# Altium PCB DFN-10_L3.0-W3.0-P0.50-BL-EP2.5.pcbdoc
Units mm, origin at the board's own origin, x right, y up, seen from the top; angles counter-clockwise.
Board outline 15.85 x 16.55 mm, 2 copper layers (Top Layer, Bottom Layer), stack 0 mm thick; 1 components, 0 nets, 11 pads, 0 vias.
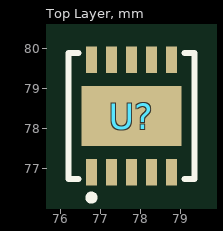
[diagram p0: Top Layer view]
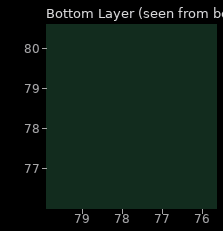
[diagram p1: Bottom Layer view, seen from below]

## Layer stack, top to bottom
Top Layer: signal copper (thickness not stored)
Bottom Layer: signal copper (thickness not stored)

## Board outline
85.702,69.85 69.85,69.85 69.85,86.405 85.702,86.405

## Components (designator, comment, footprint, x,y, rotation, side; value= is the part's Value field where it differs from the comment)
U? "" DFN-10_L3.0-W3.0-P0.50-BL-EP2.5 77.776,78.315 r0 top

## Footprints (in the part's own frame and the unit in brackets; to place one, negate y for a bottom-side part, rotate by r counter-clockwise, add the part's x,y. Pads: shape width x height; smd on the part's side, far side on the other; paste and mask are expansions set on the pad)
DFN-10_L3.0-W3.0-P0.50-BL-EP2.5 [mm]
  rect 0.28x0.665 smd paste+0 mask+0.05: 1(-1,-1.407) 2(-0.5,-1.407) 3(0,-1.407) 4(0.5,-1.407) 5(1,-1.407) 6(1,1.407) 7(0.5,1.407) 8(0,1.407) 9(-0.5,1.407) 10(-1,1.407)
  rect 2.5x1.5 smd paste+0 mask+0.05: 11(0,0)
  silkscreen extent -1.58,-2.11 1.58,1.58

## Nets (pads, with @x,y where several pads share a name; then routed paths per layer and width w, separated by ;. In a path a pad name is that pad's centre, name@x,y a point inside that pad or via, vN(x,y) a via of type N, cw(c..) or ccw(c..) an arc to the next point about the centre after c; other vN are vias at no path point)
pads on no net: U?.1 U?.2 U?.3 U?.4 U?.5 U?.6 U?.7 U?.8 U?.9 U?.10 U?.11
